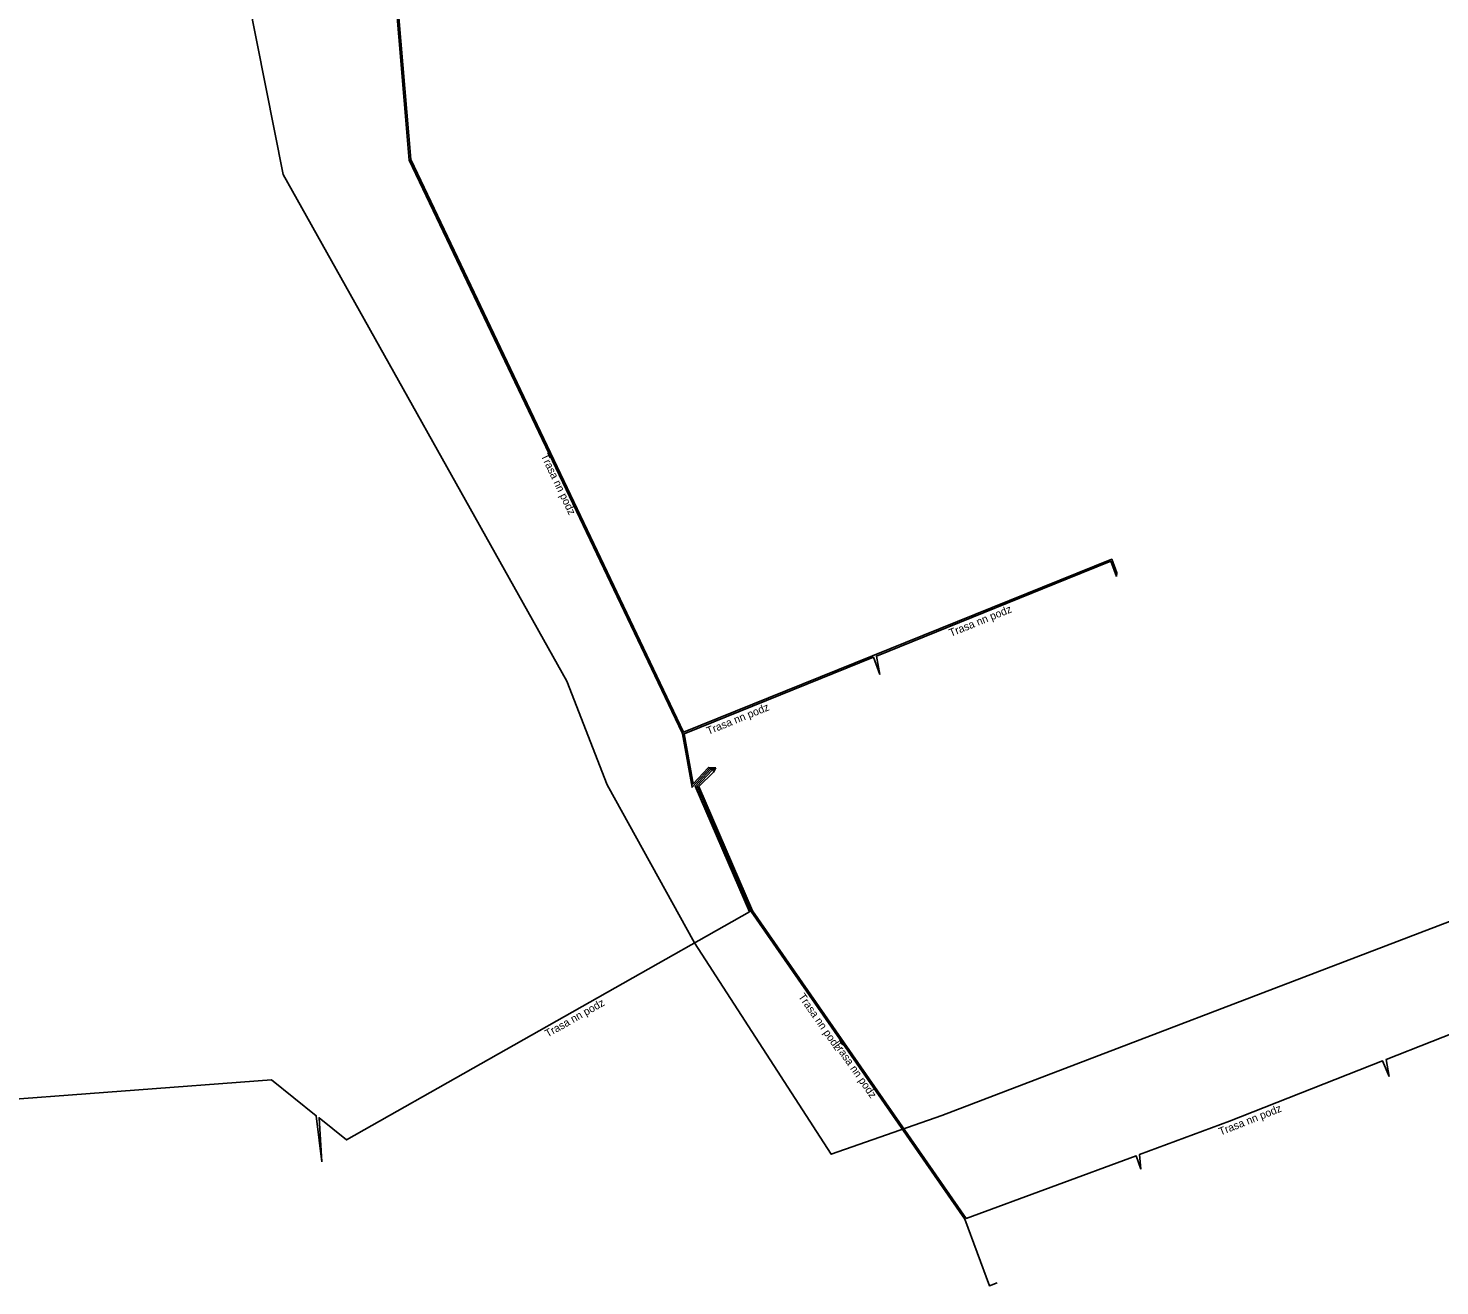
# Model space of a CAD drawing. Extents: x -873583 to -872966, y -1012951 to -1012536.
# Drawn here: x -873472.1 to -873381.3, y -1012803.9 to -1012723 of the extents above; entities that cross this region are included whole.
import ezdxf

# ---------------------------------------------------------------- set-up
doc = ezdxf.new("R2010")
doc.units = 0
for name, color, linetype in [('Popiskový text - Ostatní atributy Trasy', 7, 'Continuous'), ('Spojnice NN', 7, 'Continuous'), ('Spojnice VN', 7, 'Continuous')]:
    doc.layers.add(name, color=color, linetype=linetype)

msp = doc.modelspace()

# ---------------------------------------------------------------- linework, layer by layer
at = {"layer": 'Spojnice NN'}
for points in [[(-873427.858, -1012770.594), (-873428.264, -1012770.636), (-873429.387, -1012771.841), (-873429.992, -1012768.414), (-873430.021, -1012768.346), (-873447.579, -1012731.499), (-873448.573, -1012719.725), (-873450.034, -1012704.924), (-873456.773, -1012694.431), (-873458.348, -1012682.983), (-873469.466, -1012661.885), (-873469.688, -1012658.782), (-873470.42, -1012648.115), (-873469.405, -1012648.017), (-873469.246, -1012647.953)], [(-873402.088, -1012758.288), (-873402.065, -1012758.06), (-873402.398, -1012757.174), (-873429.93, -1012768.303), (-873447.48, -1012731.473), (-873448.383, -1012720.789), (-873448.473, -1012719.717), (-873447.223, -1012719.617), (-873437.339, -1012718.881), (-873437.249, -1012719.707)], [(-873417.31, -1012764.595), (-873417.53, -1012763.408), (-873405.266, -1012758.444), (-873402.456, -1012757.305), (-873402.088, -1012758.288)], [(-873453.198, -1012795.928), (-873453.551, -1012792.962), (-873456.424, -1012790.661), (-873475.783, -1012792.105), (-873478.006, -1012768.494), (-873478.631, -1012763.368)], [(-873427.858, -1012770.594), (-873428.336, -1012770.567), (-873429.323, -1012771.624), (-873429.504, -1012770.547), (-873429.894, -1012768.396), (-873428.888, -1012767.993), (-873417.718, -1012763.477), (-873417.31, -1012764.595)], [(-873427.858, -1012770.594), (-873428.19, -1012770.704), (-873429.176, -1012771.76), (-873425.69, -1012779.85), (-873451.613, -1012794.519), (-873453.375, -1012793.1), (-873453.198, -1012795.928)], [(-873427.858, -1012770.594), (-873428.117, -1012770.772), (-873429.058, -1012771.78), (-873425.59, -1012779.83), (-873411.84, -1012799.627), (-873410.26, -1012803.902), (-873409.768, -1012803.719)], [(-873400.529, -1012796.407), (-873400.825, -1012795.549), (-873411.758, -1012799.569), (-873425.502, -1012779.782), (-873428.94, -1012771.801), (-873428.016, -1012770.873), (-873427.858, -1012770.594)], [(-873353.522, -1012778.075), (-873353.864, -1012777.205), (-873360.14, -1012779.387), (-873378.867, -1012787.032), (-873384.738, -1012789.34), (-873384.561, -1012790.44)], [(-873384.561, -1012790.44), (-873384.981, -1012789.436), (-873394.826, -1012793.322), (-873400.614, -1012795.461), (-873400.529, -1012796.407)]]:
    msp.add_lwpolyline(points, dxfattribs=at)
at = {"layer": 'Spojnice VN'}
for points in [[(-873491.98, -1012598.14), (-873491.83, -1012599.85), (-873492.088, -1012603.505), (-873490.976, -1012613.282), (-873477.585, -1012611.672), (-873477.233, -1012616.523), (-873476.512, -1012619.584), (-873475.862, -1012635.453), (-873477.152, -1012636.637), (-873476.923, -1012647.799), (-873475.982, -1012658.878), (-873471.673, -1012684.612), (-873469.161, -1012695.58), (-873464.459, -1012705.574), (-873457.942, -1012721.062), (-873455.68, -1012732.426), (-873437.429, -1012765.017)], [(-873437.429, -1012765.017), (-873434.855, -1012771.674), (-873429.235, -1012781.85), (-873420.43, -1012795.444), (-873413.324, -1012792.951), (-873380.664, -1012780.47), (-873363.22, -1012773.365), (-873329.776, -1012760.124), (-873319.839, -1012756.433), (-873316.698, -1012765.264), (-873312.54, -1012775.807), (-873312.001, -1012777.313), (-873308.71, -1012776.033), (-873305.59, -1012774.979), (-873299.877, -1012791.486), (-873298.4, -1012795.352)]]:
    msp.add_lwpolyline(points, dxfattribs=at)

# ---------------------------------------------------------------- texts
at = {"layer": 'Popiskový text - Ostatní atributy Trasy'}
for rotation, p in [(295.47861, (-873439.124, -1012750.521)), (22.03501, (-873412.74, -1012762.171)), (22.01644, (-873428.338, -1012768.473)), (29.50378, (-873438.674, -1012787.944)), (304.78156, (-873422.578, -1012785.306)), (304.78322, (-873420.322, -1012788.379)), (21.54257, (-873395.398, -1012794.247))]:
    msp.add_text('Trasa nn podz', height=0.5, rotation=rotation, dxfattribs=at).set_placement(p)

doc.saveas('drawing.dxf')
